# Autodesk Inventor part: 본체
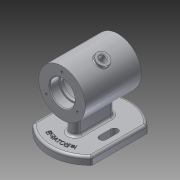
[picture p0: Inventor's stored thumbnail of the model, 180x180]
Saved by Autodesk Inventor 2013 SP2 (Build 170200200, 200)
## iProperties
Created: 2022-02
Part Number: 본체
Material: 알루미늄 6061
Document SubType Name: Modeling
Designer: i
Density: 2.71 g/cm^3
Mass: 497.101 g
Surface Area: 489.776 cm^2
Volume: 183.432 cm^3
Author: i
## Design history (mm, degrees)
sketch "스케치1"
  geometry: L1 (-36, 0)-(36, 0); L2 (-36, 0)-(-36, 30); L3 (-36, 30)-(36, 30); L4 (36, 30)-(36, 0); L5 (-36, 16)-(-24, 16); L6 (-24, 16)-(-24, 14); L7 (-24, 14)-(-20, 14); L8 (-20, 14)-(-20, 25); L9 (-20, 25)-(20, 25); L10 (20, 25)-(20, 14); L11 (20, 14)-(24, 14); L12 (24, 14)-(24, 16); L13 (24, 16)-(36, 16); 2 further points
  constraints: 26 end point, 6 perpendicular, 5 parallel, 2 point on line, 1 coincident, 1 collinear, 1 horizontal, 1 midpoint
  dimensions: "d0" = 72 distance of L1.end L1.start; "d2" = 60 diameter of L3 L1; "d3" = 32 diameter of L5 L1; "d4" = 28 diameter of L7 L1; "d5" = 50 diameter of L9 L1; "d6" = 28 diameter of L11 L1; "d7" = 32 diameter of L13 L1; "d8" = 12 distance from line of L6.end L2; "d9" = 12 distance from line of L4 L12.end; "d10" = 40 distance between parallel lines of L10 L8; "d11" = 4 distance from line of L11.end L10
revolve "회전1" sketch "스케치1" stored, may be unused: angle "d12" = 90 deg
fillet "모깎기1" dims "d13" = 0.3
fillet "모깎기2" dims "d14" = 3
chamfer "모따기1" distance "d15" = 1; stored, may be unused: second distance "d16" = 2, angle "d17" = 45 deg
sketch "스케치2"
  geometry: C1 r 30 at (0, 0) reference; 1 further point
  constraints: 1 vertical alignment
  dimensions: "d18" = 23 distance of point (0, 23) C1.centre
hole "구멍1" sketch "스케치2" at (0, 23) diameter "d19" = 3.242; stored, may be unused: countersink angle "d23" = 90 deg, drill point angle "d25" = 118 deg; dims "d20" = 8, "d21" = 4, "d22" = 2, "d24" = 10
sketch "스케치3"
  geometry: L1 (0, 0)-(28.579, 16.5); L2 (0, 0)-(33, 0); C1 r 25 at (0, 0) reference; C2 r 30 at (0, 0) reference; 2 further points
  constraints: 4 end point, 1 coincident, 1 equal length, 1 horizontal
  dimensions: "d29" = 33 distance of L1.start L1.end; "d30" = 30 deg angle of L2 L1
  node "절단 모서리 투영1"
node "작업 평면1"
sketch "스케치4"
  geometry: C1 r 8 at (0, 0); 1 further point
  constraints: 1 centre point, 1 coincident
  dimensions: "d31" = 16 diameter of C1
extrude "돌출1" join sketch "스케치4" stored distance "d32" = 10; taper "d33" = 0 deg
sketch "스케치5"
  geometry: C1 r 8 at (0, 0) reference; C2 r 4 at (0, 0)
  constraints: 1 centre point, 1 coincident
  dimensions: "d34" = 8 diameter of C2
extrude "돌출2" cut sketch "스케치5" stored distance "d35" = 10; taper "d36" = 0 deg
fillet "모깎기3" dims "d37" = 1
node "작업 평면2"
sketch "스케치6"
  geometry: L1 (-35.496, 38)-(35.496, 38); L2 (-35.496, -38)-(35.496, -38); A1 r 52 centre (0, 0) between (-35.496, 38) and (-35.496, -38); A2 r 52 centre (0, 0) between (35.496, -38) and (35.496, 38); 1 further point
  constraints: 4 end point, 4 point on circle, 2 centre point, 1 coincident, 1 horizontal, 1 parallel
  dimensions: "d43" = 76 distance between parallel lines of L2 L1; "d44" = 38 distance from line of L1 point (0, 0); "d45" = 52 radius of A1; "d46" = 52 radius of A2
extrude "돌출3" join sketch "스케치6" distance "d47" = 10; taper "d48" = 0 deg
sketch "스케치7"
  geometry: L1 (19, -7)-(-19, -7); L2 (-19, -7)-(-19, 7); L3 (-19, 7)-(19, 7); L4 (19, 7)-(19, -7); L5 (19, -7)-(-19, 7); L6 (-19, -7)-(19, 7); A1 r 52 centre (0, 0) between (-35.496, 38) and (-35.496, -38) reference; A2 r 7 centre (-19, 0) between (-19, 7) and (-19, -7); A3 r 7 centre (19, 0) between (19, -7) and (19, 7)
  constraints: 12 end point, 4 midpoint, 4 point on circle, 2 centre point, 2 parallel, 1 horizontal, 1 perpendicular
  dimensions: "d49" = 38 distance of L2.end L3.end; "d50" = 14 distance of L1.end L2.end
extrude "돌출4" join sketch "스케치7" stored distance "d51" = 0; taper "d52" = 0 deg
sketch "스케치8"
  geometry: L1 (-7.5, 28.5)-(7.5, 28.5); L2 (7.5, 28.5)-(7.5, 19.5); L3 (7.5, 19.5)-(-7.5, 19.5); L4 (-7.5, 19.5)-(-7.5, 28.5); A1 r 52 centre (0, 0) between (35.496, -38) and (35.496, 38) reference; A2 r 4.5 centre (7.5, 24) between (7.5, 19.5) and (7.5, 28.5); A3 r 4.5 centre (-7.5, 24) between (-7.5, 28.5) and (-7.5, 19.5); 1 further point
  constraints: 8 end point, 4 point on circle, 3 midpoint, 2 centre point, 2 parallel, 1 horizontal, 1 perpendicular, 1 vertical alignment
  dimensions: "d53" = 15 distance of L2.end L3.end; "d54" = 9 distance of L1.end L2.end; "d55" = 24 vertical distance of A2.centre A1.centre
extrude "돌출5" cut sketch "스케치8" stored distance "d56" = 10; taper "d57" = 0 deg
fillet "모깎기4" dims "d58" = 3
fillet "모깎기5" dims "d59" = 3
fillet "모깎기6" dims "d60" = 3
sketch "스케치10"
  geometry: C1 r 42.5 at (0, 0); A1 r 49 centre (0, 0) between (34.293, -35) and (34.293, 35) reference
  constraints: 1 centre point, 1 coincident, 1 other
  dimensions: "d65" = 85 diameter of C1
feature "엠보싱2" sketch "스케치10" dims "d0" = 72, "d2" = 60, "d3" = 32, "d4" = 28, "d5" = 50, "d6" = 28, "d7" = 32, "d8" = 12, "d9" = 12, "d10" = 40, "d11" = 4, "d14" = 3, "d66" = 0.5, "d67" = 0
fillet "모깎기7" dims "d68" = 0.3
node "솔리드1"
pattern_circular "원형 패턴1" dims angle "d27" = 360 deg
mirror "대칭1"
mirror "대칭2"
other parameters: "d38" = -62, "d42" = 104
